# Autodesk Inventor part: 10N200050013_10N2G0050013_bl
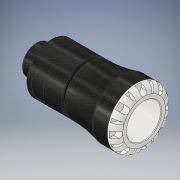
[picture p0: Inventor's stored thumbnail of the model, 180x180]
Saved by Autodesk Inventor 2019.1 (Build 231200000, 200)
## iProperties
Created: 2016-12
Part Number: 10N200050013_10N2G0050013_bl
Material: PVC-Piping
Description: PLASSON MALE ADAPTOR 50X1.1/4" SERIES 1
Document SubType Name: Modeling
Designer: KIM
Mass: 61.7504 g
Surface Area: 140.097 cm^2
Volume: 44.1074 cm^3
Density: 1.4 g/cm^3
Appearance: Black Cast
Author: KIM
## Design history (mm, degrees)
derived "10N20.ipt"
feature "Solid1::10N20.ipt" dims "ScaleForDerivedMember" = 10
tag "TaggingFeature1"
body "Solid1"
other parameters: "d0" = 158 [user parameter], "d1" = 32.76 [user parameter], "d3" = 62.5 [user parameter], "d4" = 85 [user parameter], "d6" = 78 [user parameter], "d8" = 72.25 [user parameter], "d13" = 9 [user parameter], "d14" = 9 [user parameter], "d15" = 0 [user parameter], "d17" = 360 deg [user parameter], "d19" = 8 deg [user parameter], "d20" = 1 [user parameter], "d21" = 1 [user parameter], "d22" = 8 deg [user parameter], "d24" = 0 [user parameter], "d26" = 360 deg [user parameter], "d32" = 0.925 [user parameter], "d33" = 8.5 [user parameter], "d34" = 41.91 [user parameter], "d38" = 22 [user parameter], "d39" = 1.2573 [user parameter], "d42" = 17.5 [user parameter], "d43" = 11.5 [user parameter], "d45" = 17.64 [user parameter], "d46" = 0 [user parameter], "d59" = 360 deg [user parameter], "d61" = 14.875 [user parameter], "d62" = 1 [user parameter], "d64" = 0 [user parameter], "d65" = 0.85 [user parameter], "d69" = 2 [user parameter], "d70" = 2.37 [user parameter], "d71" = 3 [user parameter], "d73" = 1 [user parameter], "E_" = 85 [user parameter], "H_" = 158 [user parameter], "l_" = 78 [user parameter], "R_" = 41.91 [user parameter], "l_2" = 22 [user parameter], "d9" = 11.25 [user parameter], "d11" = 85 [user parameter], "d12" = 62.5 [user parameter]
